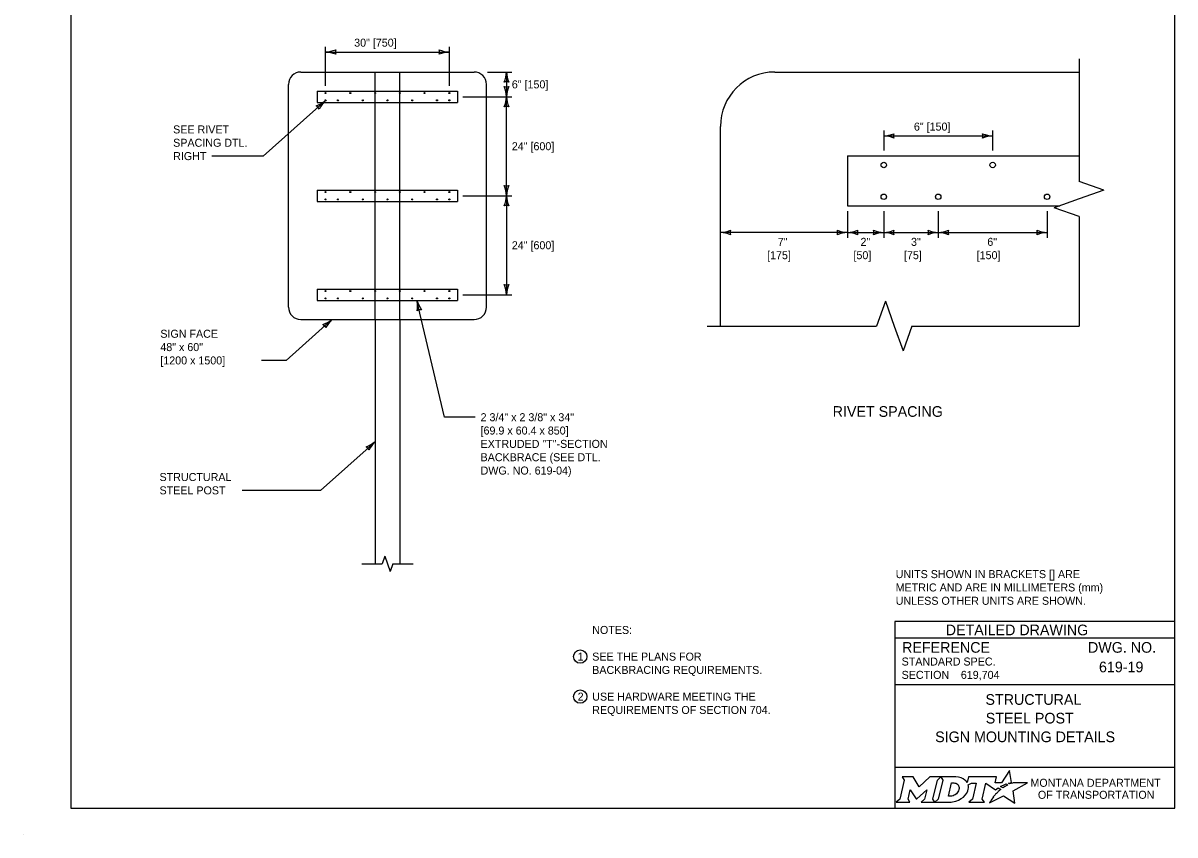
# Model space of a CAD drawing. Extents: x 49991.4 to 50021, y 49987.6 to 50011.4.
# Drawn here: x 49999.98 to 50008.61, y 49999.86 to 50005.95 of the extents above; entities that cross this region are included whole.
import ezdxf

# ---------------------------------------------------------------- set-up
doc = ezdxf.new("R2010")
doc.units = 0
for name, color, linetype in [('Level 1', 7, 'Continuous'), ('Level 2', 7, 'Continuous'), ('Level 3', 7, 'Continuous'), ('Level 4', 7, 'Continuous'), ('Level 6', 7, 'Continuous')]:
    doc.layers.add(name, color=color, linetype=linetype)

msp = doc.modelspace()

# ---------------------------------------------------------------- linework, layer by layer
at = {"layer": 'Level 1'}
for p, q in [((50002.0596, 50005.584), (50003.3589, 50005.584)), ((50005.6143, 50005.584), (50007.8953, 50005.584)), ((50001.9669, 50003.8208), (50001.9668, 50005.4913)), ((50003.4519, 50003.8208), (50003.4519, 50005.4913)), ((50005.206, 50003.6791), (50005.206, 50005.1757)), ((50002.0596, 50003.7278), (50003.3589, 50003.7278)), ((50002.6164, 50003.7278), (50002.6164, 50001.8958)), ((50002.8021, 50003.7278), (50002.8021, 50001.8958)), ((49999.9766, 49999.8624), (49999.9766, 49999.8624))]:
    msp.add_line(p, q, dxfattribs=at)
msp.add_lwpolyline([(50008.6146, 50011.2628), (50000.3356, 50011.2628), (50000.3356, 50000.0624), (50008.6146, 50000.0624)], close=True, dxfattribs=at)
for centre, radius in [((50002.2453, 50005.4256), 0.00387), ((50002.4309, 50005.4256), 0.00387), ((50002.6165, 50005.4256), 0.00387), ((50002.8021, 50005.4256), 0.00387), ((50002.9878, 50005.4256), 0.00387), ((50003.1734, 50005.4256), 0.00387), ((50002.2453, 50005.3714), 0.00387), ((50002.3381, 50005.3714), 0.00387), ((50002.5237, 50005.3714), 0.00387), ((50002.7093, 50005.3714), 0.00387), ((50002.895, 50005.3714), 0.00387), ((50003.0806, 50005.3714), 0.00387), ((50003.1734, 50005.3714), 0.00387), ((50006.4311, 50004.8865), 0.0204), ((50007.2478, 50004.8865), 0.0204), ((50002.2453, 50004.6831), 0.00387), ((50002.2453, 50004.6289), 0.00387), ((50002.3381, 50004.6289), 0.00387), ((50002.4309, 50004.6831), 0.00387), ((50002.5237, 50004.6289), 0.00387), ((50002.6165, 50004.6831), 0.00387), ((50002.7093, 50004.6289), 0.00387), ((50002.8021, 50004.6831), 0.00387), ((50002.895, 50004.6289), 0.00387), ((50002.9878, 50004.6831), 0.00387), ((50003.0806, 50004.6289), 0.00387), ((50003.1734, 50004.6831), 0.00387), ((50003.1734, 50004.6289), 0.00387), ((50006.4311, 50004.6483), 0.0204), ((50006.8394, 50004.6483), 0.0204), ((50007.6562, 50004.6483), 0.0204), ((50002.2453, 50003.9406), 0.00387), ((50002.4309, 50003.9406), 0.00387), ((50002.6165, 50003.9406), 0.00387), ((50002.8021, 50003.9406), 0.00387), ((50002.9878, 50003.9406), 0.00387), ((50003.1734, 50003.9406), 0.00387), ((50002.2453, 50003.8864), 0.00387), ((50002.3381, 50003.8864), 0.00387), ((50002.5237, 50003.8864), 0.00387), ((50002.7093, 50003.8864), 0.00387), ((50002.895, 50003.8864), 0.00387), ((50003.0806, 50003.8864), 0.00387), ((50003.1734, 50003.8864), 0.00387)]:
    msp.add_circle(centre, radius, dxfattribs=at)
for centre, radius, start, end in [((50002.0596, 50005.4913), 0.0927, 89.97427, 179.97427), ((50003.359, 50005.4911), 0.0929, 0.08445, 90.08445), ((50005.6143, 50005.1757), 0.4083, 90, 180), ((50002.0598, 50003.8207), 0.0929, 179.90744, 269.90744), ((50003.3589, 50003.8208), 0.093, 270, 0)]:
    msp.add_arc(centre, radius, start, end, dxfattribs=at)
at = {"layer": 'Level 2'}
for p, q in [((50008.6146, 50001.4624), (50006.5146, 50001.4624)), ((50006.5146, 50001.4624), (50006.5146, 50000.0624)), ((50008.6146, 50001.3374), (50006.5146, 50001.3374)), ((50008.2507, 50001.1223), (50008.2507, 50001.1223)), ((50008.6146, 50000.9874), (50006.5146, 50000.9874)), ((50007.0089, 50001.0629), (50007.0089, 50001.0629)), ((50007.5646, 50000.7383), (50007.5646, 50000.7383)), ((50008.6146, 50000.3693), (50006.5146, 50000.3693))]:
    msp.add_line(p, q, dxfattribs=at)
for points in [[(50006.5701, 50000.2974), (50006.5842, 50000.274), (50006.5507, 50000.1307), (50006.525, 50000.1082), (50006.6266, 50000.1082), (50006.6131, 50000.131), (50006.6293, 50000.2011), (50006.673, 50000.1321), (50006.6783, 50000.1321), (50006.7534, 50000.2016), (50006.737, 50000.1305), (50006.7123, 50000.1085), (50006.8139, 50000.1085), (50006.8001, 50000.1318), (50006.8333, 50000.2742)], [(50006.8333, 50000.2742), (50006.8586, 50000.2974), (50006.7762, 50000.2974), (50006.6966, 50000.2244), (50006.6521, 50000.2971), (50006.5701, 50000.2974)], [(50006.9722, 50000.2974), (50006.8586, 50000.2974), (50006.8733, 50000.2745), (50006.8394, 50000.1307), (50006.8139, 50000.1085), (50006.9245, 50000.1085)], [(50007.3771, 50000.2447), (50007.3668, 50000.2503), (50007.3784, 50000.2531), (50007.39, 50000.2551), (50007.3726, 50000.3452), (50007.3131, 50000.2539), (50007.2658, 50000.2532), (50007.2761, 50000.2973), (50007.0669, 50000.2974), (50007.0568, 50000.2549), (50007.051, 50000.2632)], [(50006.9962, 50000.2107), (50006.995, 50000.2026), (50006.9918, 50000.1933), (50006.9876, 50000.1851), (50006.982, 50000.1776), (50006.9755, 50000.1707), (50006.9676, 50000.1644), (50006.9593, 50000.1597), (50006.9502, 50000.1558), (50006.9411, 50000.1535), (50006.9319, 50000.1526), (50006.916, 50000.1526), (50006.9396, 50000.2526), (50006.9556, 50000.2526), (50006.9632, 50000.252), (50006.9708, 50000.2501), (50006.9774, 50000.2471), (50006.9835, 50000.2429), (50006.9883, 50000.2379), (50006.992, 50000.2319), (50006.9947, 50000.2257), (50006.9963, 50000.2183), (50006.9963, 50000.2153), (50006.9962, 50000.2107)], [(50007.0636, 50000.2383), (50007.0882, 50000.2514), (50007.1251, 50000.2514), (50007.0965, 50000.1309), (50007.069, 50000.1082), (50007.1852, 50000.1082), (50007.1682, 50000.1311), (50007.1964, 50000.2513), (50007.2677, 50000.1996), (50007.2888, 50000.2147), (50007.3085, 50000.2038)], [(50007.2527, 50000.1479), (50007.2374, 50000.1235), (50007.2327, 50000.116), (50007.2269, 50000.1074), (50007.2246, 50000.1031), (50007.3299, 50000.1562), (50007.4138, 50000.1011), (50007.4007, 50000.1938), (50007.5076, 50000.2522), (50007.4583, 50000.253), (50007.4282, 50000.2534), (50007.4074, 50000.2537), (50007.4006, 50000.2522), (50007.3957, 50000.251), (50007.3873, 50000.2487), (50007.3771, 50000.2447)], [(50007.3267, 50000.2171), (50007.3243, 50000.2154), (50007.306, 50000.225), (50007.3163, 50000.2307), (50007.3204, 50000.2329), (50007.329, 50000.2369), (50007.3347, 50000.2395), (50007.3426, 50000.2425), (50007.3499, 50000.2452), (50007.3617, 50000.2378), (50007.3577, 50000.2357), (50007.3531, 50000.2332), (50007.3489, 50000.231), (50007.3439, 50000.2281), (50007.342, 50000.227), (50007.3393, 50000.2254), (50007.3368, 50000.224), (50007.3345, 50000.2224), (50007.3319, 50000.2206), (50007.3292, 50000.2188), (50007.3267, 50000.2171)], [(50006.9702, 50000.1158), (50006.9786, 50000.1184), (50006.9916, 50000.1238), (50007.012, 50000.1348)], [(50007.2666, 50000.164), (50007.2666, 50000.164)]]:
    msp.add_lwpolyline(points, dxfattribs=at)
for centre in [(50004.1549, 50001.1999), (50004.1549, 50000.8999)]:
    msp.add_circle(centre, 0.05, dxfattribs=at)
for centre, radius, start, end in [((50006.9953, 50000.219), 0.0709, 339.53292, 15.85821), ((50006.9513, 50000.2363), 0.1183, 300.91025, 339.13831)]:
    msp.add_arc(centre, radius, start, end, dxfattribs=at)
for centre, major_axis, ratio, start_param, end_param in [((50006.9701, 50000.25), (0.0834, -0.0037), 0.568097, 0.61298, 1.570796), ((50007.0257, 50000.2573), (0.0361, -0.0295), 0.469099, 1.225588, 1.570796), ((50007.2974, 50000.1941), (-0.0112, -0.0097), 0.021651, 3.157348, 6.283185), ((50006.9248, 50000.2568), (0, 0.1484), 0.987302, 3.139398, 3.456847), ((50007.2597, 50000.1559), (-0.00694, -0.00806), 0.008222, 0, 3.137361), ((50007.2764, 50000.1742), (-0.0098, -0.0102), 0.016458, 3.141593, 6.279097)]:
    msp.add_ellipse(centre, major_axis=major_axis, ratio=ratio, start_param=start_param, end_param=end_param, dxfattribs=at)
at = {"layer": 'Level 3'}
for p, q in [((50002.2453, 50005.481), (50002.2453, 50005.774)), ((50002.2453, 50005.734), (50003.1734, 50005.734)), ((50003.1734, 50005.481), (50003.1734, 50005.774)), ((50003.4592, 50005.584), (50003.6419, 50005.584)), ((50003.6019, 50005.584), (50003.6019, 50005.3985)), ((50003.2753, 50005.3985), (50003.6419, 50005.3985)), ((50003.6019, 50004.656), (50003.6019, 50005.3985)), ((50002.2427, 50005.3686), (50001.7766, 50004.9534)), ((50006.4311, 50005.1445), (50006.4311, 50004.9945)), ((50007.2478, 50004.9945), (50007.2478, 50005.1445)), ((50006.4311, 50005.1045), (50007.2478, 50005.1045)), ((50001.7766, 50004.9534), (50001.3917, 50004.9534)), ((50003.2753, 50004.656), (50003.6419, 50004.656)), ((50003.6019, 50004.656), (50003.6019, 50003.9135)), ((50006.1589, 50004.5403), (50006.1589, 50004.3403)), ((50006.4311, 50004.5403), (50006.4311, 50004.3403)), ((50006.8394, 50004.5403), (50006.8394, 50004.3403)), ((50007.6562, 50004.5403), (50007.6562, 50004.3403)), ((50006.1589, 50004.3803), (50005.206, 50004.3803)), ((50006.1589, 50004.3803), (50006.4311, 50004.3803)), ((50006.4311, 50004.3803), (50006.8394, 50004.3803)), ((50006.8394, 50004.3803), (50007.6562, 50004.3803)), ((50003.1375, 50002.9952), (50002.9306, 50003.871)), ((50003.2753, 50003.9135), (50003.6419, 50003.9135)), ((50002.2932, 50003.7278), (50001.9488, 50003.4211)), ((50001.9488, 50003.4211), (50001.7647, 50003.4211)), ((50003.3676, 50002.9952), (50003.1375, 50002.9952)), ((50002.6164, 50002.8118), (50002.2064, 50002.4466)), ((50002.2064, 50002.4466), (50001.6194, 50002.4466))]:
    msp.add_line(p, q, dxfattribs=at)
for centre, radius, start, end in [((50002.2338, 50005.9667), 0.233, 272.82731, 292.07716), ((50002.2361, 50005.5119), 0.2223, 67.45601, 87.63952), ((50002.3735, 50005.734), 0.0548, 162.13882, 197.86118), ((50003.1826, 50005.9561), 0.2223, 247.45601, 267.63952), ((50003.0452, 50005.734), 0.0548, 342.13882, 17.86118), ((50003.1849, 50005.5013), 0.233, 92.82731, 112.07716), ((50003.3798, 50005.5932), 0.2223, 337.45601, 357.63952), ((50003.8346, 50005.5955), 0.233, 182.82731, 202.07716), ((50003.6019, 50005.4558), 0.0548, 72.13882, 107.86118), ((50003.6019, 50005.5267), 0.0548, 252.13882, 287.86118), ((50003.3692, 50005.387), 0.233, 2.82731, 22.07716), ((50003.824, 50005.3893), 0.2223, 157.45601, 177.63952), ((50003.3798, 50005.4077), 0.2223, 337.45601, 357.63952), ((50003.8346, 50005.41), 0.233, 182.82731, 202.07716), ((50002.1018, 50005.5405), 0.2223, 289.14848, 309.33199), ((50002.1469, 50005.2833), 0.0548, 23.83129, 59.55365), ((50002.406, 50005.2024), 0.233, 134.51978, 153.76963), ((50003.6019, 50005.2703), 0.0548, 72.13882, 107.86118), ((50006.4196, 50005.3372), 0.233, 272.82731, 292.07716), ((50006.4219, 50004.8824), 0.2223, 67.45601, 87.63952), ((50006.5593, 50005.1045), 0.0548, 162.13882, 197.86118), ((50007.257, 50005.3266), 0.2223, 247.45601, 267.63952), ((50007.1196, 50005.1045), 0.0548, 342.13882, 17.86118), ((50007.2593, 50004.8718), 0.233, 92.82731, 112.07716), ((50003.6019, 50004.7842), 0.0548, 252.13882, 287.86118), ((50003.3692, 50004.6445), 0.233, 2.82731, 22.07716), ((50003.824, 50004.6468), 0.2223, 157.45601, 177.63952), ((50003.3798, 50004.6652), 0.2223, 337.45601, 357.63952), ((50003.8346, 50004.6675), 0.233, 182.82731, 202.07716), ((50003.6019, 50004.5278), 0.0548, 72.13882, 107.86118), ((50005.1945, 50004.613), 0.233, 272.82731, 292.07716), ((50005.1968, 50004.1582), 0.2223, 67.45601, 87.63952), ((50005.3342, 50004.3803), 0.0548, 162.13882, 197.86118), ((50006.1681, 50004.6024), 0.2223, 247.45601, 267.63952), ((50006.0307, 50004.3803), 0.0548, 342.13882, 17.86118), ((50006.1704, 50004.1476), 0.233, 92.82731, 112.07716), ((50006.1474, 50004.613), 0.233, 272.82731, 292.07716), ((50006.1497, 50004.1582), 0.2223, 67.45601, 87.63952), ((50006.2871, 50004.3803), 0.0548, 162.13882, 197.86118), ((50006.4403, 50004.6024), 0.2223, 247.45601, 267.63952), ((50006.3029, 50004.3803), 0.0548, 342.13882, 17.86118), ((50006.4426, 50004.1476), 0.233, 92.82731, 112.07716), ((50006.4196, 50004.613), 0.233, 272.82731, 292.07716), ((50006.4219, 50004.1582), 0.2223, 67.45601, 87.63952), ((50006.5593, 50004.3803), 0.0548, 162.13882, 197.86118), ((50006.8486, 50004.6024), 0.2223, 247.45601, 267.63952), ((50006.7112, 50004.3803), 0.0548, 342.13882, 17.86118), ((50006.8509, 50004.1476), 0.233, 92.82731, 112.07716), ((50006.8279, 50004.613), 0.233, 272.82731, 292.07716), ((50006.8302, 50004.1582), 0.2223, 67.45601, 87.63952), ((50006.9676, 50004.3803), 0.0548, 162.13882, 197.86118), ((50007.6654, 50004.6024), 0.2223, 247.45601, 267.63952), ((50007.528, 50004.3803), 0.0548, 342.13882, 17.86118), ((50007.6677, 50004.1476), 0.233, 92.82731, 112.07716), ((50003.6019, 50004.0417), 0.0548, 252.13882, 287.86118), ((50003.3692, 50003.902), 0.233, 2.82731, 22.07716), ((50003.824, 50003.9043), 0.2223, 157.45601, 177.63952), ((50002.7123, 50003.8288), 0.2223, 350.74793, 10.93144), ((50003.1544, 50003.9357), 0.233, 196.11923, 215.36908), ((50002.9601, 50003.7462), 0.0548, 85.43074, 121.1531), ((50002.1523, 50003.8998), 0.2223, 289.14848, 309.33199), ((50002.1975, 50003.6425), 0.0548, 23.83129, 59.55365), ((50002.4566, 50003.5617), 0.233, 134.51978, 153.76963), ((50002.4755, 50002.9838), 0.2223, 289.14848, 309.33199), ((50002.7798, 50002.6457), 0.233, 134.51978, 153.76963), ((50002.5207, 50002.7265), 0.0548, 23.83129, 59.55365)]:
    msp.add_arc(centre, radius, start, end, dxfattribs=at)
at = {"layer": 'Level 4'}
for p, q in [((50002.6164, 50003.7278), (50002.6164, 50005.584)), ((50002.8021, 50003.7278), (50002.8021, 50005.584)), ((50002.1834, 50005.441), (50002.1834, 50005.356)), ((50002.1834, 50005.441), (50003.2353, 50005.441)), ((50003.2353, 50005.441), (50003.2353, 50005.356)), ((50002.1834, 50005.356), (50003.2353, 50005.356)), ((50006.1588, 50004.9545), (50006.1588, 50004.5803)), ((50006.1588, 50004.9545), (50007.8953, 50004.9545)), ((50002.1834, 50004.6986), (50002.1834, 50004.6135)), ((50002.1834, 50004.6986), (50003.2353, 50004.6986)), ((50003.2353, 50004.6986), (50003.2353, 50004.6135)), ((50002.1834, 50004.6135), (50003.2353, 50004.6135)), ((50006.1588, 50004.5803), (50007.7503, 50004.5803)), ((50002.1834, 50003.956), (50002.1834, 50003.871)), ((50002.1834, 50003.956), (50003.2353, 50003.956)), ((50003.2353, 50003.956), (50003.2353, 50003.871)), ((50002.1834, 50003.871), (50003.2353, 50003.871))]:
    msp.add_line(p, q, dxfattribs=at)
at = {"layer": 'Level 6'}
for p, q in [((50007.8953, 50005.684), (50007.8953, 50004.764)), ((50008.0817, 50004.6978), (50007.8953, 50004.764)), ((50008.0817, 50004.6978), (50007.8953, 50004.6317)), ((50007.8953, 50004.6317), (50007.7086, 50004.5655)), ((50007.8953, 50004.4993), (50007.7086, 50004.5655)), ((50007.8953, 50004.4993), (50007.8953, 50003.6791)), ((50006.4438, 50003.8656), (50006.3776, 50003.6791)), ((50006.4438, 50003.8656), (50006.5098, 50003.6791)), ((50005.106, 50003.6791), (50006.3776, 50003.6791)), ((50006.5098, 50003.6791), (50006.576, 50003.4924)), ((50006.6422, 50003.6791), (50006.576, 50003.4924)), ((50006.6422, 50003.6791), (50007.8953, 50003.6791)), ((50002.6893, 50001.9524), (50002.6692, 50001.8958)), ((50002.6893, 50001.9524), (50002.7094, 50001.8958)), ((50002.5164, 50001.8958), (50002.6692, 50001.8958)), ((50002.7094, 50001.8958), (50002.7293, 50001.8393)), ((50002.7494, 50001.8958), (50002.7293, 50001.8393)), ((50002.7494, 50001.8958), (50002.9021, 50001.8958))]:
    msp.add_line(p, q, dxfattribs=at)

# ---------------------------------------------------------------- texts
at = {"layer": 'Level 2'}
for s, height, p in [('30" [750]', 0.06, (50002.4597, 50005.774)), ('6" [150]', 0.06, (50003.6419, 50005.4613)), ('SEE RIVET ', 0.06, (50001.1024, 50005.1234)), ('6" [150]', 0.06, (50006.657, 50005.1445)), ('SPACING DTL.', 0.06, (50001.1024, 50005.0234)), ('24" [600]', 0.06, (50003.6419, 50004.9973)), ('RIGHT', 0.06, (50001.1024, 50004.9234)), ('24" [600]', 0.06, (50003.6419, 50004.2548)), ('7"', 0.06, (50005.6361, 50004.2803)), ('2"', 0.06, (50006.2567, 50004.2803)), ('3"', 0.06, (50006.6355, 50004.2803)), ('6"', 0.06, (50007.2075, 50004.2803)), ('[175]', 0.06, (50005.5562, 50004.1803)), ('[50]', 0.06, (50006.2038, 50004.1803)), ('[75]', 0.06, (50006.5826, 50004.1803)), ('[150]', 0.06, (50007.1276, 50004.1803)), ('SIGN FACE', 0.06, (50001.0061, 50003.5911)), ('48" x 60"', 0.06, (50001.0061, 50003.4911)), ('[1200 x 1500]', 0.06, (50001.0061, 50003.3911)), ('RIVET SPACING', 0.08, (50006.0478, 50002.9981)), ('2 3/4" x 2 3/8" x 34"', 0.06, (50003.4076, 50002.9652)), ('[69.9 x 60.4 x 850]', 0.06, (50003.4076, 50002.8652)), ('EXTRUDED "T"-SECTION', 0.06, (50003.4076, 50002.7652)), ('BACKBRACE (SEE DTL.', 0.06, (50003.4076, 50002.6652)), ('DWG. NO. 619-04)', 0.06, (50003.4076, 50002.5652)), ('STRUCTURAL', 0.06, (50001.0002, 50002.5166)), ('STEEL POST', 0.06, (50001.0002, 50002.4166)), ('UNITS SHOWN IN BRACKETS [] ARE ', 0.06, (50006.5203, 50001.7886)), ('METRIC AND ARE IN MILLIMETERS (mm) ', 0.06, (50006.5203, 50001.6886)), ('UNLESS OTHER UNITS ARE SHOWN.', 0.06, (50006.5203, 50001.5886)), ('NOTES:', 0.06, (50004.2449, 50001.3699)), ('DETAILED DRAWING', 0.0799, (50006.8956, 50001.3599)), ('REFERENCE', 0.08, (50006.5682, 50001.229)), ('DWG. NO.', 0.08, (50007.9624, 50001.229)), ('1', 0.06, (50004.1356, 50001.1699)), ('SEE THE PLANS FOR', 0.06, (50004.2449, 50001.1699)), ('STANDARD SPEC.', 0.06, (50006.5649, 50001.133)), ('619-19', 0.08, (50008.0448, 50001.0823)), ('BACKBRACING REQUIREMENTS.', 0.06, (50004.2449, 50001.0699)), ('SECTION', 0.06, (50006.5649, 50001.033)), ('619,704', 0.06, (50007.0089, 50001.0329)), ('2', 0.06, (50004.1356, 50000.8699)), ('USE HARDWARE MEETING THE', 0.06, (50004.2449, 50000.8699)), ('STRUCTURAL', 0.08, (50007.1936, 50000.8383)), ('REQUIREMENTS OF SECTION 704.', 0.06, (50004.2449, 50000.7699)), ('STEEL POST', 0.08, (50007.1957, 50000.6983)), ('SIGN MOUNTING DETAILS', 0.08, (50006.8164, 50000.5583)), ('MONTANA DEPARTMENT', 0.06, (50007.5308, 50000.2236)), ('OF TRANSPORTATION', 0.06, (50007.587, 50000.1336))]:
    msp.add_text(s, height=height, dxfattribs=at).set_placement(p)

doc.saveas('drawing.dxf')
